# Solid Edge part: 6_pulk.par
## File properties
Author: Romil
Template: iso part.par
Last saved by: Romil
Revision: 33
Application: Solid Edge
Accuracy: 0.990
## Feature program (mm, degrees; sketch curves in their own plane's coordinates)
sketch for "unnamed Protrusion 1" plane through (0, 0, 0) normal (1, 0, 0) x-axis (0, 1, 0)
  arc centre (0, 0) radius 2.35 from (2.181, 0.875) to (2.181, -0.875) cw
  arc centre (0, 0) radius 2.35 from (-0.875, 2.181) to (0.875, 2.181) cw
  arc centre (0, 0) radius 2.35 from (-2.181, -0.875) to (-2.181, 0.875) cw
extrude "unnamed Protrusion 1" add finite 37.2 symmetric
fillet "Round_4" radius 0.55  Radii2 = 0.2 mm
mirror "unnamed Mirror 1" of "Round_4" about plane through (0, 0, 0) normal (1, 0, 0)
fillet "unnamed Round 1"
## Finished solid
Body 1: solid body, 50 faces, 128 edges, 80 vertices.
  Faces by surface: cylinder 24, torus 16, plane 10
  Edges by curve: circle 48, line 48, intersection 32
Bounding box of the edges (mm; curved faces can reach further): 37.200 x 4.700 x 4.700, from (-18.6, -2.35, -2.35) to (18.6, 2.35, 2.35).
Cylindrical faces by radius (mm): R0.1 x4, R0.2 x16, R2.35 x4
Toroidal faces (ring radius, tube radius in mm): R0.3 r0.2 x8, R1.8 r0.55 x8
Planar faces by outward normal: +x 1, +y 2, +z 2, -x 1, -y 2, -z 2
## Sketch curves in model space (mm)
arc centre (0, -0.975, -0.975) radius 0.1 from (0, -0.975, -0.875) through (0, -0.9023, -0.9064) to (0, -0.875, -0.975)
line (0, -0.875, -0.975) -> (0, -0.875, -2.181)
arc centre (0, 0, 0) radius 2.35 from (0, 0.875, -2.181) through (0, 0, -2.35) to (0, -0.875, -2.181)
line (0, 0.875, -2.181) -> (0, 0.875, -0.975)
arc centre (0, 0.975, -0.975) radius 0.1 from (0, 0.875, -0.975) through (0, 0.9064, -0.9023) to (0, 0.975, -0.875)
line (0, 0.975, -0.875) -> (0, 2.181, -0.875)
arc centre (0, 0, 0) radius 2.35 from (0, 2.181, 0.875) through (0, 2.35, 0) to (0, 2.181, -0.875)
line (0, 2.181, 0.875) -> (0, 0.975, 0.875)
arc centre (0, 0.975, 0.975) radius 0.1 from (0, 0.975, 0.875) through (0, 0.9023, 0.9064) to (0, 0.875, 0.975)
line (0, 0.875, 0.975) -> (0, 0.875, 2.181)
arc centre (0, 0, 0) radius 2.35 from (0, -0.875, 2.181) through (0, 0, 2.35) to (0, 0.875, 2.181)
line (0, -0.875, 2.181) -> (0, -0.875, 0.975)
arc centre (0, -0.975, 0.975) radius 0.1 from (0, -0.875, 0.975) through (0, -0.9064, 0.9023) to (0, -0.975, 0.875)
line (0, -0.975, 0.875) -> (0, -2.181, 0.875)
arc centre (0, 0, 0) radius 2.35 from (0, -2.181, -0.875) through (0, -2.35, 0) to (0, -2.181, 0.875)
line (0, -2.181, -0.875) -> (0, -0.975, -0.875)
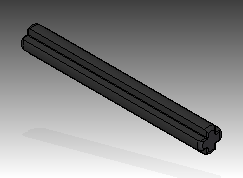
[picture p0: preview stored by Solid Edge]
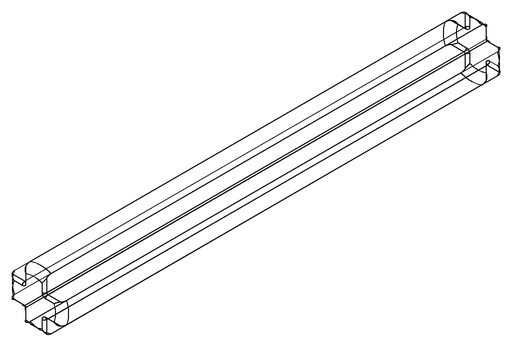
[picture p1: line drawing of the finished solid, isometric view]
